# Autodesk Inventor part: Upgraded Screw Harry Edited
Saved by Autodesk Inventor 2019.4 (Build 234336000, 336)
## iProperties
Created: 2020-06
Part Number: Upgraded Screw Harry Edited
Material: Generic
Document SubType Name: Modeling
Designer: Administrator
Density: 1 g/cm^3
Appearance: Default
Title: Upgraded Screw Harry Edited v16
Author: Administrator
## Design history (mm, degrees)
feature "Main Body"
body "Solid1"
